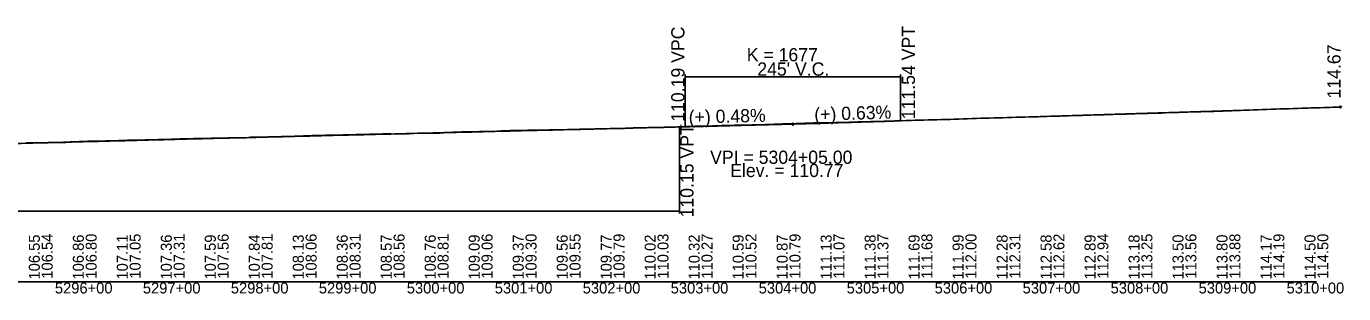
# Model space of a CAD drawing. Extents: x 2121671 to 2169879, y 557274 to 599957.
# Drawn here: x 2159102 to 2160599, y 576173 to 576477 of the extents above; entities that cross this region are included whole.
import ezdxf

# ---------------------------------------------------------------- set-up
doc = ezdxf.new("R2010")
doc.units = 0
for name, color, linetype in [('RD_DDB_GradeTX', 7, 'Continuous'), ('RD_DDB_Profile_EX', 7, 'Continuous'), ('RD_DDB_Profile_Lbl', 7, 'Continuous'), ('RD_DDB_Profile_PR', 7, 'Continuous'), ('RD_DDB_StaTX', 7, 'Continuous'), ('RD_DDB_StripGrade', 7, 'Continuous'), ('RD_DDB_VCLbl', 7, 'Continuous'), ('RD_GPK_Profile_Cell', 7, 'Continuous')]:
    doc.layers.add(name, color=color, linetype=linetype)

msp = doc.modelspace()

# ---------------------------------------------------------------- linework, layer by layer
at = {"layer": 'RD_DDB_GradeTX'}
for p, q in [((2159911, 576364.2), (2159971.9, 576365.7)), ((2160034.9, 576367.6), (2159973.9, 576365.7))]:
    msp.add_line(p, q, dxfattribs=at)
for centre in [(2160595.4, 576385.2), (2159972.9, 576365.7)]:
    msp.add_circle(centre, 1, dxfattribs=at)
at = {"layer": 'RD_DDB_Profile_EX'}
for points in [[(2159986.5, 576366.8), (2159991.5, 576367), (2159996.5, 576367.1), (2160001.5, 576367.2), (2160006.5, 576367.3), (2160011.5, 576367.4), (2160016.5, 576367.4), (2160021.5, 576367.5), (2160026.5, 576367.6), (2160031.5, 576367.7), (2160036.5, 576367.9), (2160041.5, 576368.1), (2160046.5, 576368.2), (2160051.5, 576368.3), (2160056.5, 576368.4), (2160061.5, 576368.6), (2160066.5, 576368.7), (2160071.5, 576368.8), (2160076.5, 576369), (2160081.5, 576369.2), (2160086.5, 576369.3), (2160091.5, 576369.5), (2160096.5, 576369.6), (2160101.5, 576369.8), (2160106.5, 576370), (2160111.5, 576370.1), (2160116.5, 576370.2), (2160121.5, 576370.4), (2160126.5, 576370.5), (2160131.5, 576370.6), (2160136.5, 576370.8), (2160141.5, 576370.9), (2160146.5, 576371.1), (2160151.5, 576371.2), (2160156.5, 576371.4), (2160161.5, 576371.6), (2160166.5, 576371.7), (2160171.5, 576371.9), (2160176.5, 576372.1), (2160181.5, 576372.3), (2160186.5, 576372.4), (2160191.5, 576372.6), (2160196.5, 576372.7), (2160201.5, 576372.8), (2160206.5, 576373), (2160211.5, 576373.1), (2160216.5, 576373.2), (2160221.5, 576373.3), (2160226.5, 576373.5), (2160231.5, 576373.6), (2160236.5, 576373.8), (2160241.5, 576373.9), (2160246.5, 576374.1), (2160251.5, 576374.2), (2160256.5, 576374.4), (2160261.5, 576374.5), (2160266.5, 576374.7), (2160271.5, 576374.9), (2160276.5, 576375), (2160281.5, 576375.1), (2160286.5, 576375.2), (2160291.5, 576375.4), (2160296.5, 576375.5), (2160301.5, 576375.7), (2160306.5, 576375.9), (2160311.5, 576376.1), (2160316.5, 576376.2), (2160321.5, 576376.4), (2160326.5, 576376.5), (2160331.5, 576376.7), (2160336.5, 576376.8), (2160341.5, 576377), (2160346.5, 576377.1), (2160351.5, 576377.2), (2160356.5, 576377.4), (2160361.5, 576377.5), (2160366.5, 576377.7), (2160371.5, 576377.8), (2160376.5, 576378), (2160381.5, 576378.1), (2160386.5, 576378.3), (2160391.5, 576378.4), (2160396.5, 576378.6), (2160401.5, 576378.8), (2160406.5, 576378.9), (2160411.5, 576379.1), (2160416.5, 576379.3), (2160421.5, 576379.4), (2160426.5, 576379.6), (2160431.5, 576379.7), (2160436.5, 576379.9), (2160441.5, 576380), (2160446.5, 576380.2), (2160451.5, 576380.3), (2160456.5, 576380.5), (2160461.5, 576380.6), (2160466.5, 576380.8), (2160471.5, 576381), (2160476.5, 576381.2), (2160481.5, 576381.4), (2160486.5, 576381.6)], [(2160486.5, 576381.6), (2160491.5, 576381.7), (2160496.5, 576381.9), (2160501.5, 576382.1), (2160506.5, 576382.3), (2160511.5, 576382.5), (2160516.5, 576382.6), (2160521.5, 576382.8), (2160526.5, 576383), (2160531.5, 576383.2), (2160536.5, 576383.3), (2160541.5, 576383.5), (2160546.5, 576383.7), (2160551.5, 576383.8), (2160556.5, 576384), (2160561.5, 576384.1), (2160566.5, 576384.3), (2160571.5, 576384.4), (2160576.5, 576384.6), (2160581.5, 576384.7), (2160586.5, 576384.9), (2160591.5, 576385.1), (2160595.4, 576385.2)], [(2159486.5, 576354.1), (2159491.5, 576354.2), (2159496.5, 576354.4), (2159501.5, 576354.5), (2159506.5, 576354.7), (2159511.5, 576354.8), (2159516.5, 576354.8), (2159521.5, 576354.5), (2159526.5, 576354.6), (2159531.5, 576354.8), (2159536.5, 576354.9), (2159541.5, 576355.3), (2159546.5, 576355.5), (2159551.5, 576355.6), (2159556.5, 576355.7), (2159561.5, 576355.6), (2159566.5, 576355.6), (2159571.5, 576355.7), (2159576.5, 576355.9), (2159581.5, 576356.3), (2159586.5, 576356.7), (2159591.5, 576356.8), (2159596.5, 576356.9), (2159601.5, 576357), (2159606.5, 576357.1), (2159611.5, 576357.2), (2159616.5, 576357.3), (2159621.5, 576357.3), (2159626.5, 576357.4), (2159631.5, 576357.6), (2159636.5, 576357.7), (2159641.5, 576358.1), (2159646.5, 576358.2), (2159651.5, 576358.4), (2159656.5, 576358.5), (2159661.5, 576358.7), (2159666.5, 576358.6), (2159671.5, 576358.8), (2159676.5, 576358.9), (2159681.5, 576359), (2159686.5, 576359.1), (2159691.5, 576359.1), (2159696.5, 576359.2), (2159701.5, 576359.3), (2159706.5, 576359.4), (2159711.5, 576359.4), (2159716.5, 576359.6), (2159721.5, 576359.6), (2159726.5, 576359.7), (2159731.5, 576359.8), (2159736.5, 576359.9), (2159741.5, 576360.1), (2159746.5, 576360.2), (2159751.5, 576360.4), (2159756.5, 576360.5), (2159761.5, 576360.6), (2159766.5, 576360.7), (2159771.5, 576360.8), (2159776.5, 576360.9), (2159781.5, 576361), (2159786.5, 576361.3), (2159791.5, 576361.5), (2159796.5, 576361.5), (2159801.5, 576361.6), (2159806.5, 576361.7), (2159811.5, 576361.8), (2159816.5, 576361.9), (2159821.5, 576362), (2159826.5, 576362.1), (2159831.5, 576362.3), (2159836.5, 576362.4), (2159841.5, 576362.6), (2159846.5, 576362.8), (2159851.5, 576363), (2159856.5, 576363.1), (2159861.5, 576363.3), (2159866.5, 576363.4), (2159871.5, 576363.5), (2159876.5, 576363.6), (2159881.5, 576363.8), (2159886.5, 576364), (2159891.5, 576364.1), (2159896.5, 576364.2), (2159901.5, 576364.4), (2159906.5, 576364.5), (2159911.5, 576364.5), (2159916.5, 576364.8), (2159921.5, 576364.7), (2159926.5, 576364.9), (2159931.5, 576365), (2159936.5, 576365.1), (2159941.5, 576365.2), (2159946.5, 576365.5), (2159951.5, 576365.7), (2159956.5, 576365.8), (2159961.5, 576366), (2159966.5, 576366.1), (2159971.5, 576366.3), (2159976.5, 576366.5), (2159981.5, 576366.6), (2159986.5, 576366.8)], [(2159101.5, 576344.4), (2159106.5, 576344.4), (2159111.5, 576344.6), (2159116.5, 576344.5), (2159121.5, 576344.6), (2159126.5, 576344.7), (2159131.5, 576344.9), (2159136.5, 576345), (2159141.5, 576345), (2159146.5, 576345.1), (2159151.5, 576345.7), (2159156.5, 576345.8), (2159161.5, 576345.9), (2159166.5, 576346.1), (2159171.5, 576346.3), (2159176.5, 576346.4), (2159181.5, 576346.5), (2159186.5, 576346.6), (2159191.5, 576346.7), (2159196.5, 576346.9), (2159201.5, 576347), (2159206.5, 576347.1), (2159211.5, 576347.3), (2159216.5, 576347.4), (2159221.5, 576347.5), (2159226.5, 576347.5), (2159231.5, 576347.7), (2159236.5, 576347.8), (2159241.5, 576347.9), (2159246.5, 576348.1), (2159251.5, 576348.2), (2159256.5, 576348.3), (2159261.5, 576348.5), (2159266.5, 576348.6), (2159271.5, 576348.8), (2159276.5, 576348.9), (2159281.5, 576349), (2159286.5, 576349.1), (2159291.5, 576349.3), (2159296.5, 576349.4), (2159301.5, 576349.5), (2159306.5, 576349.6), (2159311.5, 576349.8), (2159316.5, 576349.8), (2159321.5, 576349.8), (2159326.5, 576350), (2159331.5, 576350.1), (2159336.5, 576350.3), (2159341.5, 576350.4), (2159346.5, 576350.4), (2159351.5, 576350.2), (2159356.5, 576350.8), (2159361.5, 576350.9), (2159366.5, 576351), (2159371.5, 576351.1), (2159376.5, 576351.2), (2159381.5, 576351.3), (2159386.5, 576351.4), (2159391.5, 576351.6), (2159396.5, 576351.8), (2159401.5, 576351.9), (2159406.5, 576352.1), (2159411.5, 576352.3), (2159416.5, 576352.4), (2159421.5, 576352.6), (2159426.5, 576352.7), (2159431.5, 576352.8), (2159436.5, 576352.9), (2159441.5, 576353.1), (2159446.5, 576353.2), (2159451.5, 576353.3), (2159456.5, 576353.4), (2159461.5, 576353.5), (2159466.5, 576353.6), (2159471.5, 576353.7), (2159476.5, 576353.9), (2159481.5, 576354), (2159486.5, 576354.1)]]:
    msp.add_lwpolyline(points, dxfattribs=at)
at = {"layer": 'RD_DDB_Profile_PR'}
for p, q in [((2160095.3, 576369.5), (2160595.4, 576385.2)), ((2159843.9, 576362.6), (2159850.6, 576362.8))]:
    msp.add_line(p, q, dxfattribs=at)
for points in [[(2159850.6, 576362.8), (2159855.5, 576362.9), (2159860.4, 576363), (2159865.3, 576363.1), (2159870.2, 576363.2), (2159875.1, 576363.4), (2159880, 576363.5), (2159884.9, 576363.6), (2159889.7, 576363.7), (2159894.6, 576363.8), (2159899.5, 576364), (2159904.4, 576364.1), (2159909.3, 576364.2), (2159914.2, 576364.4), (2159919.1, 576364.5), (2159924, 576364.6), (2159928.9, 576364.7), (2159933.8, 576364.9), (2159938.7, 576365), (2159943.6, 576365.1), (2159948.5, 576365.3), (2159953.4, 576365.4), (2159958.3, 576365.5), (2159963.1, 576365.7), (2159968, 576365.8), (2159972.9, 576365.9), (2159977.8, 576366.1), (2159982.7, 576366.2), (2159987.6, 576366.3), (2159992.5, 576366.5), (2159997.4, 576366.6), (2160002.3, 576366.7), (2160007.2, 576366.9), (2160012.1, 576367), (2160017, 576367.2), (2160021.9, 576367.3), (2160026.8, 576367.5), (2160031.7, 576367.6), (2160036.5, 576367.7), (2160041.4, 576367.9), (2160046.3, 576368), (2160051.2, 576368.2), (2160056.1, 576368.3), (2160061, 576368.5), (2160065.9, 576368.6), (2160070.8, 576368.8), (2160075.7, 576368.9), (2160080.6, 576369.1), (2160085.5, 576369.2), (2160090.4, 576369.4), (2160095.3, 576369.5)], [(2158093.9, 576316.9), (2158128.9, 576317.9), (2158163.9, 576318.9), (2158198.9, 576319.9), (2158233.9, 576320.9), (2158268.9, 576321.8), (2158303.9, 576322.8), (2158338.9, 576323.8), (2158373.9, 576324.7), (2158408.9, 576325.7), (2158443.9, 576326.7), (2158478.9, 576327.6), (2158513.9, 576328.6), (2158548.9, 576329.5), (2158583.9, 576330.5), (2158618.9, 576331.4), (2158653.9, 576332.3), (2158688.9, 576333.3), (2158723.9, 576334.2), (2158758.9, 576335.1), (2158793.9, 576336.1), (2158828.9, 576337), (2158863.9, 576337.9), (2158898.9, 576338.8), (2158933.9, 576339.8), (2158968.9, 576340.7), (2159003.9, 576341.6), (2159038.9, 576342.5), (2159073.9, 576343.4), (2159108.9, 576344.3), (2159143.9, 576345.2), (2159178.9, 576346.1), (2159213.9, 576347), (2159248.9, 576347.9), (2159283.9, 576348.8), (2159318.9, 576349.7), (2159353.9, 576350.5), (2159388.9, 576351.4), (2159423.9, 576352.3), (2159458.9, 576353.2), (2159493.9, 576354), (2159528.9, 576354.9), (2159563.9, 576355.8), (2159598.9, 576356.6), (2159633.9, 576357.5), (2159668.9, 576358.4), (2159703.9, 576359.2), (2159738.9, 576360.1), (2159773.9, 576360.9), (2159808.9, 576361.8), (2159843.9, 576362.6)]]:
    msp.add_spline(points, degree=3, dxfattribs=at)
at = {"layer": 'RD_DDB_VCLbl'}
for p, q in [((2159850.6, 576422), (2159850.6, 576362.8)), ((2159850.6, 576419.5), (2160095.3, 576419.5)), ((2160095.3, 576422), (2160095.3, 576369.5)), ((2159843.9, 576264.4), (2159843.9, 576362.6)), ((2158093.9, 576266.9), (2159843.9, 576266.9))]:
    msp.add_line(p, q, dxfattribs=at)
at = {"layer": 'RD_GPK_Profile_Cell'}
msp.add_line((2157367.9, 576186.8), (2160567.9, 576186.8), dxfattribs=at)

# ---------------------------------------------------------------- texts
at = {"layer": 'RD_DDB_GradeTX'}
for s, rotation, p in [('(+) 0.48%', 1.3765, (2159854.6, 576366.3)), ('(+) 0.63%', 1.7942, (2159997.4, 576369.4))]:
    msp.add_text(s, height=15, rotation=rotation, dxfattribs=at).set_placement(p)
at = {"layer": 'RD_DDB_Profile_Lbl'}
msp.add_text('114.67', height=15, rotation=90, dxfattribs=at).set_placement((2160595.4, 576394.8))
for s, p in [('VPI = 5304+05.00', (2159878.8, 576320.7)), ('Elev. = 110.77', (2159901.6, 576305.7))]:
    msp.add_text(s, height=15, dxfattribs=at).set_placement(p)
at = {"layer": 'RD_DDB_StaTX'}
for s, p in [('5296+00', (2159134, 576173.5)), ('5297+00', (2159234, 576173.5)), ('5298+00', (2159334, 576173.5)), ('5299+00', (2159434, 576173.5)), ('5300+00', (2159534, 576173.5)), ('5301+00', (2159634, 576173.5)), ('5302+00', (2159734, 576173.5)), ('5303+00', (2159834, 576173.5)), ('5304+00', (2159934, 576173.5)), ('5305+00', (2160034, 576173.5)), ('5306+00', (2160134, 576173.5)), ('5307+00', (2160234, 576173.5)), ('5308+00', (2160334, 576173.5)), ('5309+00', (2160434, 576173.5)), ('5310+00', (2160534, 576173.5))]:
    msp.add_text(s, height=12.5, dxfattribs=at).set_placement(p)
at = {"layer": 'RD_DDB_StripGrade'}
for s, height, p in [('110.19 VPC', 15, (2159849.6, 576368.4)), ('111.54 VPT', 15, (2160111.6, 576371.3)), ('110.15 VPT', 15, (2159859.9, 576259.8)), ('106.55', 12.5, (2159116.9, 576189.3)), ('106.54', 12.5, (2159131.5, 576190.3)), ('106.86', 12.5, (2159166.9, 576189.3)), ('106.80', 12.5, (2159181.5, 576190.3)), ('107.11', 12.5, (2159216.9, 576189.3)), ('107.05', 12.5, (2159231.5, 576190.3)), ('107.36', 12.5, (2159266.9, 576189.3)), ('107.31', 12.5, (2159281.5, 576190.3)), ('107.59', 12.5, (2159316.9, 576189.3)), ('107.56', 12.5, (2159331.5, 576190.3)), ('107.84', 12.5, (2159366.9, 576189.3)), ('107.81', 12.5, (2159381.5, 576190.3)), ('108.13', 12.5, (2159416.9, 576189.3)), ('108.06', 12.5, (2159431.5, 576190.3)), ('108.36', 12.5, (2159466.9, 576189.3)), ('108.31', 12.5, (2159481.5, 576190.3)), ('108.57', 12.5, (2159516.9, 576189.3)), ('108.56', 12.5, (2159531.5, 576190.3)), ('108.76', 12.5, (2159566.9, 576189.3)), ('108.81', 12.5, (2159581.5, 576190.3)), ('109.09', 12.5, (2159616.9, 576189.3)), ('109.06', 12.5, (2159631.5, 576190.3)), ('109.37', 12.5, (2159666.9, 576189.3)), ('109.30', 12.5, (2159681.5, 576190.3)), ('109.56', 12.5, (2159716.9, 576189.3)), ('109.55', 12.5, (2159731.5, 576190.3)), ('109.77', 12.5, (2159766.9, 576189.3)), ('109.79', 12.5, (2159781.5, 576190.3)), ('110.02', 12.5, (2159816.9, 576189.3)), ('110.03', 12.5, (2159831.5, 576190.3)), ('110.32', 12.5, (2159866.9, 576189.3)), ('110.27', 12.5, (2159881.5, 576190.3)), ('110.59', 12.5, (2159916.9, 576189.3)), ('110.52', 12.5, (2159931.5, 576190.3)), ('110.87', 12.5, (2159966.9, 576189.3)), ('110.79', 12.5, (2159981.5, 576190.3)), ('111.13', 12.5, (2160016.9, 576189.3)), ('111.07', 12.5, (2160031.5, 576190.3)), ('111.38', 12.5, (2160066.9, 576189.3)), ('111.37', 12.5, (2160081.5, 576190.3)), ('111.69', 12.5, (2160116.9, 576189.3)), ('111.68', 12.5, (2160131.5, 576190.3)), ('111.99', 12.5, (2160166.9, 576189.3)), ('112.00', 12.5, (2160181.5, 576190.3)), ('112.28', 12.5, (2160216.9, 576189.3)), ('112.31', 12.5, (2160231.5, 576190.3)), ('112.58', 12.5, (2160266.9, 576189.3)), ('112.62', 12.5, (2160281.5, 576190.3)), ('112.89', 12.5, (2160316.9, 576189.3)), ('112.94', 12.5, (2160331.5, 576190.3)), ('113.18', 12.5, (2160366.9, 576189.3)), ('113.25', 12.5, (2160381.5, 576190.3)), ('113.50', 12.5, (2160416.9, 576189.3)), ('113.56', 12.5, (2160431.5, 576190.3)), ('113.80', 12.5, (2160466.9, 576189.3)), ('113.88', 12.5, (2160481.5, 576190.3)), ('114.17', 12.5, (2160516.9, 576189.3)), ('114.19', 12.5, (2160531.5, 576190.3)), ('114.50', 12.5, (2160566.9, 576189.3)), ('114.50', 12.5, (2160581.5, 576190.3))]:
    msp.add_text(s, height=height, rotation=90, dxfattribs=at).set_placement(p)
at = {"layer": 'RD_DDB_VCLbl'}
for s, p in [('K = 1677', (2159920.4, 576437.1)), ("245' V.C.", (2159932.4, 576420.8))]:
    msp.add_text(s, height=15, dxfattribs=at).set_placement(p)

doc.saveas('drawing.dxf')
